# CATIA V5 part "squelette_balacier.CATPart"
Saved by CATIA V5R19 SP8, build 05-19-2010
Part number: squelette_balancier
Publications: "Droite.1", "Droite.2", "Plan.1"
Bounding box of the stored display mesh (mm): x 83 to 83, y 246.609 to 269.066, z 59.697 to 112.052
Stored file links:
  G:\EU_thinkMotion\CFAO_2010\MMS_groupe3\MMS_groupe3\A reprendre\amenand\amenand\squelette_balacier.CATPart
  F:\thinkmotion CFAO v12.1\essuie_glace.CATProduct
  G:\EU_thinkMotion\CFAO_2010\MMS_groupe3\MMS_groupe3\A reprendre\amenand\amenand\squelette_bati.CATPart
  G:\EU_thinkMotion\CFAO_2010\MMS_groupe3\MMS_groupe3\A reprendre\amenand\amenand\squelette_biellette2.CATPart
  G:\EU_thinkMotion\CFAO_2010\MMS_groupe3\MMS_groupe3\A reprendre\amenand\amenand\squelette_biellette1.CATPart
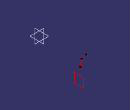
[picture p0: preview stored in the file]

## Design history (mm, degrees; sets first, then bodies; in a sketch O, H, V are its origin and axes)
Set1
  Plane1: linked copy from another document
  Point1 to Point3: linked copy from another document
Set2 "set géométrique.7"
  Line1: type PtPt, FirstPoint Point1, SecondPoint Point2
  Line2: type PtPt, FirstPoint Point1, SecondPoint Point3
Body1 (main body)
